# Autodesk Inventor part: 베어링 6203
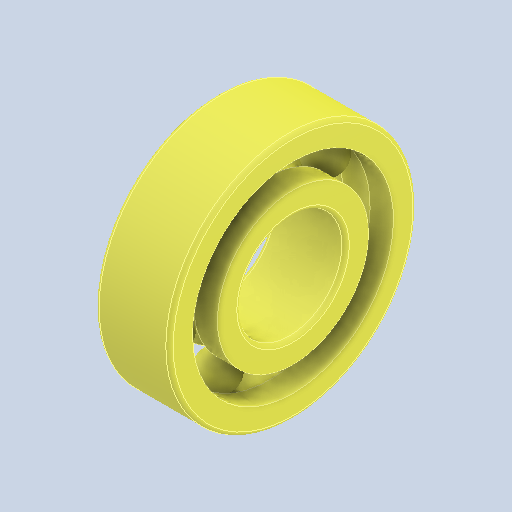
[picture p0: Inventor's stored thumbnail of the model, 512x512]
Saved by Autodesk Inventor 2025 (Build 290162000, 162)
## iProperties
Created: 2024-07
Part Number: 베어링 6203
Material: 강철, 연강
Description: 깊은 그루브 볼 베어링
Document SubType Name: Modeling
Designer: 학생
Density: 7.86 g/cm^3
Appearance: 기본값
Author: jhkim
Revision Number: 1
Sending System: Autodesk Inventor 2025
Preprocessor: ST-DEVELOPER v20
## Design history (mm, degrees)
feature "Solid1"
feature "Solid1:1"
feature "Solid1:2"
feature "Solid1:3"
feature "Solid1:4"
feature "Solid1:5"
feature "Solid1:6"
feature "Solid1:7"
feature "Solid1:8"
node "솔리드1"
node "솔리드2"
node "솔리드3"
node "솔리드4"
node "솔리드5"
node "솔리드6"
node "솔리드7"
node "솔리드8"
node "솔리드9"
